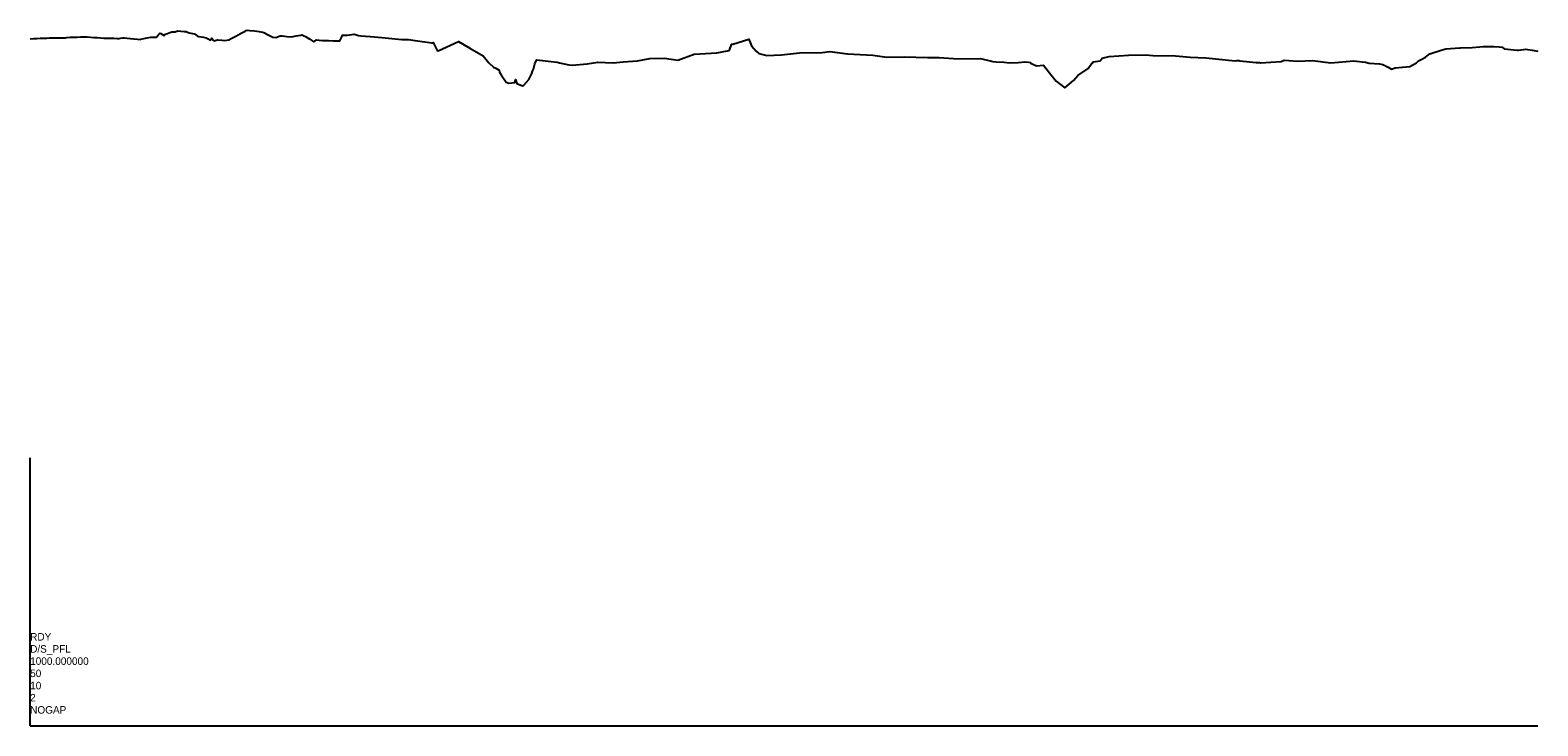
# Model space of a CAD drawing. Extents: x 1726619 to 1729848, y 535683 to 539687.
# Drawn here: x 1726619 to 1728026, y 535683 to 536332 of the extents above; entities that cross this region are included whole.
import ezdxf

# ---------------------------------------------------------------- set-up
doc = ezdxf.new("R2010")
doc.units = 0
doc.layers.add('Exist Profile Cell', color=7, linetype='Continuous')
doc.layers.add('Prop DSN Text', color=7, linetype='Continuous')

msp = doc.modelspace()

# ---------------------------------------------------------------- linework, layer by layer
at = {"layer": 'Exist Profile Cell'}
for q in [(1726618.5, 535932.8), (1728026.3, 535682.8), (1726618.5, 535682.8)]:
    msp.add_line((1726618.5, 535682.8), q, dxfattribs=at)
at = {"layer": 'Prop DSN Text'}
msp.add_lwpolyline([(1726618.5, 536324.1), (1726621.6, 536324.2), (1726624.8, 536324.3), (1726627.9, 536324.5), (1726631, 536324.6), (1726634.1, 536324.7), (1726636.4, 536324.8), (1726637.3, 536324.8), (1726640.4, 536324.9), (1726643.5, 536324.9), (1726646.6, 536324.9), (1726649.8, 536325), (1726651.6, 536325), (1726652.9, 536325.1), (1726656, 536325.4), (1726659.2, 536325.5), (1726662.3, 536325.6), (1726665.4, 536325.8), (1726668.5, 536325.9), (1726671.7, 536325.7), (1726674.8, 536325.5), (1726677.9, 536325.3), (1726681, 536325.1), (1726684.2, 536324.8), (1726687.3, 536324.6), (1726689.3, 536324.5), (1726690.4, 536324.5), (1726693.5, 536324.5), (1726696.7, 536324.5), (1726699.8, 536324.4), (1726701.6, 536324.4), (1726702.9, 536324.6), (1726705.4, 536325), (1726706.2, 536324.8), (1726709.2, 536324.6), (1726712.3, 536324.3), (1726715.4, 536324.1), (1726718.6, 536323.8), (1726721.4, 536323.5), (1726721.7, 536323.6), (1726724.8, 536324.2), (1726727.9, 536324.8), (1726731.3, 536325.4), (1726734.2, 536325.4), (1726736.4, 536325.4), (1726737.3, 536326.7), (1726738.9, 536328.8), (1726739.5, 536329.4), (1726740.4, 536328.9), (1726743.6, 536327.1), (1726744.5, 536328.2), (1726746.7, 536329), (1726749.8, 536330.2), (1726750.9, 536330.6), (1726753, 536330.5), (1726754, 536330.4), (1726756.1, 536331.3), (1726759.2, 536331.1), (1726762.3, 536330.9), (1726764.3, 536330.7), (1726765.5, 536330.2), (1726766.9, 536329.6), (1726768.6, 536329.3), (1726771.7, 536328.7), (1726772.1, 536328.7), (1726774.5, 536326.8), (1726775.2, 536326.5), (1726776, 536326.3), (1726780.4, 536325.4), (1726783, 536324.8), (1726784.7, 536323.9), (1726786.9, 536322.7), (1726787.5, 536323.5), (1726788.1, 536324.5), (1726789.1, 536322.7), (1726789.9, 536322.1), (1726793.3, 536322.9), (1726793.7, 536323), (1726797.7, 536322.7), (1726800.2, 536322.4), (1726802, 536322.7), (1726804, 536323.1), (1726806.3, 536324.3), (1726810.6, 536326.6), (1726815, 536328.9), (1726819.3, 536331.2), (1726820.3, 536331.8), (1726821.2, 536332.1), (1726823.6, 536331.8), (1726827.9, 536331.3), (1726832.3, 536330.7), (1726835.6, 536330.3), (1726836.6, 536329.8), (1726840.9, 536327.6), (1726844.4, 536325.7), (1726845.2, 536325.6), (1726848.1, 536325.2), (1726849.6, 536325.8), (1726852.1, 536326.8), (1726853.9, 536326.7), (1726858.2, 536326.3), (1726862.5, 536326), (1726866.9, 536326.8), (1726871.2, 536327.5), (1726872.1, 536327.7), (1726873.8, 536327.1), (1726874.2, 536326.9), (1726875.6, 536326.3), (1726879.8, 536323.6), (1726883.5, 536321.2), (1726884.2, 536321.7), (1726885.9, 536323), (1726888.5, 536322.8), (1726891.4, 536322.5), (1726892.8, 536322.5), (1726897.1, 536322.3), (1726901.5, 536322.2), (1726905.8, 536322.1), (1726907.7, 536322), (1726909.5, 536326), (1726910, 536327.3), (1726913.4, 536327.4), (1726914.4, 536327.5), (1726918.8, 536328), (1726921.2, 536328.3), (1726923.1, 536327.7), (1726925.2, 536327.1), (1726927.4, 536326.9), (1726931.7, 536326.5), (1726936.1, 536326.1), (1726946.8, 536325.2), (1726965.6, 536323.5), (1726971.7, 536323.4), (1726978, 536322.3), (1726993.6, 536320.2), (1726994.6, 536320.3), (1726994.8, 536320.6), (1726998.7, 536313.2), (1726999.5, 536312.7), (1727018.5, 536321.6), (1727022.2, 536319.3), (1727029.1, 536315.2), (1727041.6, 536308.2), (1727046.8, 536301.7), (1727051, 536297.5), (1727053.3, 536296.7), (1727056.3, 536294.7), (1727056.9, 536293), (1727058.3, 536290.4), (1727063, 536283.5), (1727065.6, 536282.7), (1727071.2, 536283.3), (1727071.6, 536285.9), (1727073, 536282.3), (1727078.2, 536280), (1727079.4, 536280.8), (1727084.1, 536286.1), (1727085, 536287.8), (1727087, 536291.7), (1727087.5, 536293.8), (1727088.4, 536295.8), (1727089.9, 536300.6), (1727091.2, 536304), (1727091.4, 536304.3), (1727110.5, 536302.1), (1727112.7, 536301.5), (1727121.4, 536299.8), (1727124.5, 536299.5), (1727138.6, 536300.5), (1727148.5, 536302.2), (1727163, 536301.7), (1727172.3, 536302.4), (1727185.7, 536303.3), (1727197.1, 536305.6), (1727210.8, 536305.9), (1727223.2, 536304.2), (1727238.4, 536309.8), (1727259.7, 536311), (1727271.2, 536313.1), (1727271.5, 536313.5), (1727273.4, 536318.6), (1727273.7, 536319), (1727274.5, 536319.1), (1727289.7, 536323.6), (1727292.1, 536317.4), (1727296.5, 536312.4), (1727299, 536310.4), (1727306.5, 536308.5), (1727320.1, 536309), (1727337, 536311), (1727357.9, 536311.2), (1727365.2, 536312.1), (1727381.8, 536310), (1727405.4, 536308.6), (1727418.4, 536307), (1727434.8, 536307.1), (1727456.4, 536306.6), (1727467.4, 536306.7), (1727484.9, 536305.4), (1727505.9, 536305.5), (1727517.4, 536302.8), (1727520.6, 536302.5), (1727528.1, 536302.2), (1727532.8, 536301.7), (1727541.1, 536301.8), (1727547.5, 536302.6), (1727550.7, 536302.2), (1727552.6, 536301.9), (1727553.2, 536300.9), (1727554.2, 536300.7), (1727558.1, 536298.7), (1727564.7, 536299.3), (1727570.3, 536292.4), (1727576.4, 536284.6), (1727584.5, 536278.1), (1727592.7, 536285.2), (1727596.7, 536289.9), (1727606.5, 536296.3), (1727609.9, 536301.3), (1727610.6, 536301.7), (1727611.2, 536302.4), (1727617.5, 536303.5), (1727619.6, 536305.8), (1727625.9, 536307.5), (1727644, 536308.7), (1727660.3, 536309), (1727666.9, 536308.5), (1727688.1, 536308.1), (1727701.8, 536306.8), (1727716.3, 536306.1), (1727743.8, 536303.6), (1727745.3, 536303.9), (1727746.6, 536303.9), (1727747.3, 536303.8), (1727748, 536303.5), (1727763.4, 536301.9), (1727766.4, 536302), (1727767.4, 536301.7), (1727786.5, 536302.9), (1727789.4, 536304), (1727802.2, 536303.2), (1727815.8, 536303.7), (1727833.1, 536301.6), (1727854.6, 536303.6), (1727862.2, 536302.6), (1727865.1, 536302.2), (1727865.5, 536302.3), (1727868.7, 536301.4), (1727878.5, 536300.8), (1727881.7, 536300.1), (1727886.4, 536297.5), (1727889.5, 536295.6), (1727893.2, 536297), (1727906.8, 536298.1), (1727913.1, 536301.5), (1727914.5, 536303.2), (1727914.9, 536303.3), (1727918, 536305), (1727921.4, 536306.9), (1727925.4, 536309.9), (1727936, 536313.4), (1727940.5, 536314.8), (1727953.4, 536315.6), (1727954.1, 536315.6), (1727965.1, 536316), (1727972.1, 536316.5), (1727975.4, 536316.8), (1727985.3, 536316.9), (1727990.2, 536316.5), (1727993, 536316.3), (1727994.8, 536314.7), (1728007.1, 536313.3), (1728008.3, 536313.4), (1728015, 536314.4), (1728021.1, 536313.4), (1728026.3, 536312.5)], dxfattribs=at)

# ---------------------------------------------------------------- texts
at = {"layer": 'Exist Profile Cell'}
for s, p in [('RDY', (1726618.5, 535762.4)), ('D/S_PFL', (1726618.5, 535751.1)), ('1000.000000', (1726618.5, 535739.7)), ('50', (1726618.5, 535728.3)), ('2', (1726618.5, 535705.6)), ('10', (1726618.5, 535716.9)), ('NOGAP', (1726618.5, 535694.2))]:
    msp.add_text(s, height=7, dxfattribs=at).set_placement(p)

doc.saveas('drawing.dxf')
